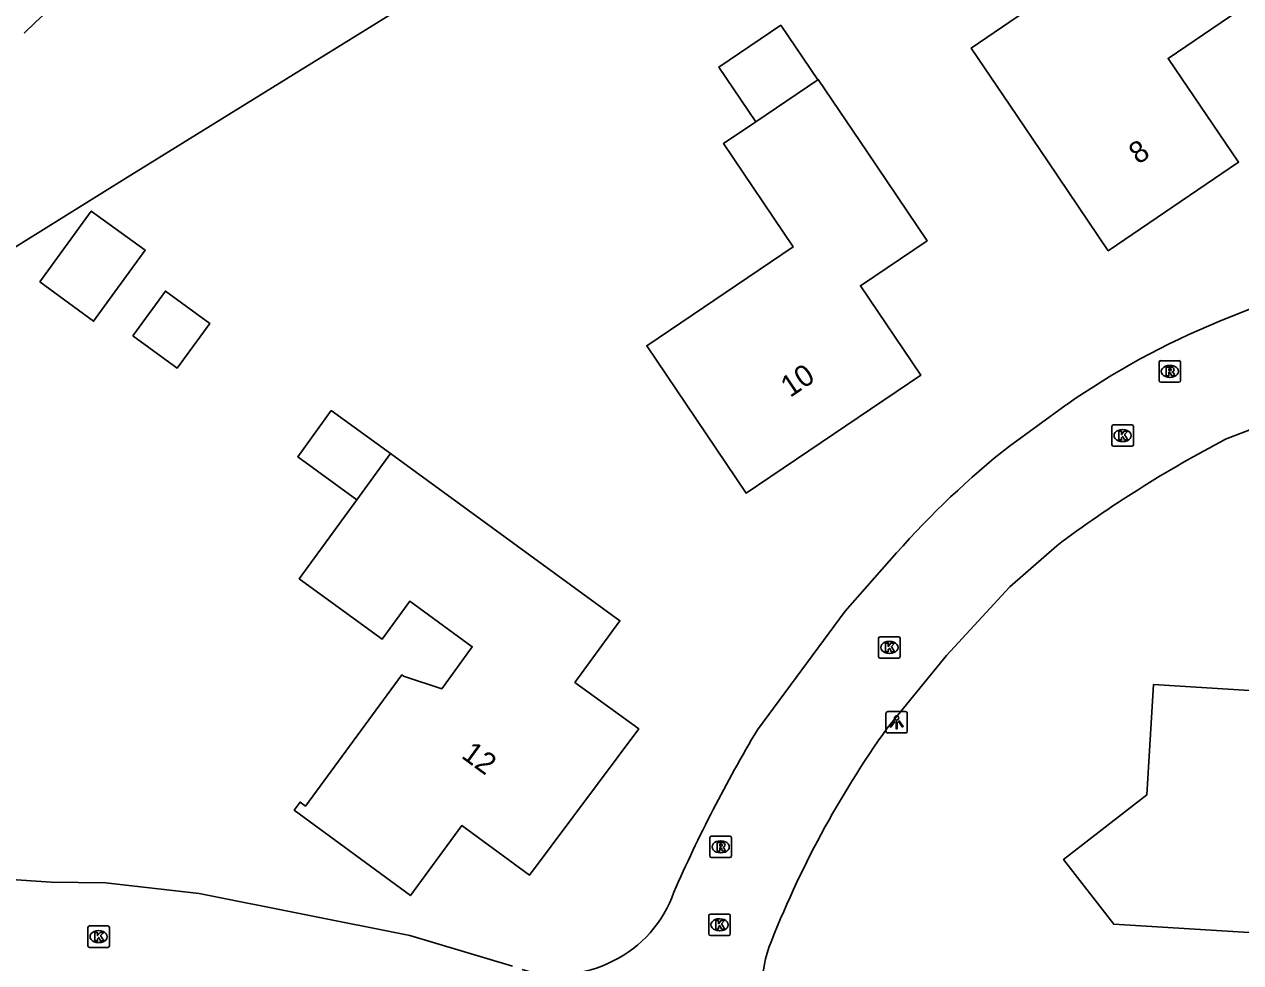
# Model space of a CAD drawing. Extents: x 163268 to 164360, y 381529 to 382285.
# Drawn here: x 163454.1 to 163510.8, y 381660.1 to 381703.8 of the extents above; entities that cross this region are included whole.
import ezdxf

# ---------------------------------------------------------------- set-up
doc = ezdxf.new("R2010")
doc.units = 0
for name, color, linetype in [('IMGEO_Kolk', 7, 'Continuous'), ('IMGEO_Lichtpunt', 7, 'Continuous'), ('IMGEO_Loofbos', 7, 'Continuous'), ('IMGEO_Pand', 7, 'Continuous'), ('IMGEO_Pand_nummerreeks', 7, 'Continuous'), ('IMGEO_Rijbaan_lokaal_open', 7, 'Continuous'), ('IMGEO_Rioolput', 7, 'Continuous'), ('IMGEO_Voetpad_halfverhard', 7, 'Continuous')]:
    doc.layers.add(name, color=color, linetype=linetype)

msp = doc.modelspace()

# ---------------------------------------------------------------- linework, layer by layer
at = {"layer": 'IMGEO_Kolk'}
for p, q in [((163504.757, 381684.204), (163504.757, 381685.056)), ((163504.832, 381685.13), (163505.684, 381685.13)), ((163505.245, 381684.91), (163505.27, 381684.91)), ((163505.758, 381685.056), (163505.758, 381684.204)), ((163505.268, 381684.35), (163505.243, 381684.35)), ((163505.684, 381684.13), (163504.832, 381684.13)), ((163493.89, 381674.335), (163493.89, 381675.187)), ((163493.965, 381675.261), (163494.817, 381675.261)), ((163494.891, 381675.187), (163494.891, 381674.335)), ((163494.378, 381675.041), (163494.403, 381675.041)), ((163494.817, 381674.261), (163493.965, 381674.261)), ((163494.401, 381674.481), (163494.376, 381674.481)), ((163485.977, 381661.414), (163485.977, 381662.266)), ((163486.052, 381662.34), (163486.904, 381662.34)), ((163486.465, 381662.12), (163486.49, 381662.12)), ((163486.978, 381662.266), (163486.978, 381661.414)), ((163457.045, 381660.862), (163457.045, 381661.714)), ((163457.12, 381661.788), (163457.972, 381661.788)), ((163457.533, 381661.568), (163457.558, 381661.568)), ((163458.046, 381661.714), (163458.046, 381660.862)), ((163486.488, 381661.56), (163486.463, 381661.56)), ((163457.556, 381661.008), (163457.531, 381661.008)), ((163486.904, 381661.34), (163486.052, 381661.34)), ((163457.972, 381660.788), (163457.12, 381660.788))]:
    msp.add_line(p, q, dxfattribs=at)
for points in [[(163504.757, 381684.204), (163504.757, 381685.056)], [(163504.832, 381685.13), (163505.684, 381685.13)], [(163505.078, 381684.83), (163505.201, 381684.83), (163505.201, 381684.679), (163505.331, 381684.83), (163505.495, 381684.83), (163505.349, 381684.679), (163505.502, 381684.43), (163505.35, 381684.43), (163505.265, 381684.594), (163505.201, 381684.527), (163505.201, 381684.43), (163505.078, 381684.43), (163505.078, 381684.83)], [(163505.758, 381685.056), (163505.758, 381684.204)], [(163505.684, 381684.13), (163504.832, 381684.13)], [(163493.89, 381674.335), (163493.89, 381675.187)], [(163493.965, 381675.261), (163494.817, 381675.261)], [(163494.891, 381675.187), (163494.891, 381674.335)], [(163494.211, 381674.961), (163494.334, 381674.961), (163494.334, 381674.81), (163494.464, 381674.961), (163494.628, 381674.961), (163494.482, 381674.81), (163494.635, 381674.561), (163494.483, 381674.561), (163494.398, 381674.725), (163494.334, 381674.658), (163494.334, 381674.561), (163494.211, 381674.561), (163494.211, 381674.961)], [(163494.817, 381674.261), (163493.965, 381674.261)], [(163485.977, 381661.414), (163485.977, 381662.266)], [(163486.052, 381662.34), (163486.904, 381662.34)], [(163486.978, 381662.266), (163486.978, 381661.414)], [(163457.045, 381660.862), (163457.045, 381661.714)], [(163457.12, 381661.788), (163457.972, 381661.788)], [(163458.046, 381661.714), (163458.046, 381660.862)], [(163486.298, 381662.04), (163486.421, 381662.04), (163486.421, 381661.889), (163486.551, 381662.04), (163486.715, 381662.04), (163486.569, 381661.889), (163486.722, 381661.64), (163486.57, 381661.64), (163486.485, 381661.804), (163486.421, 381661.737), (163486.421, 381661.64), (163486.298, 381661.64), (163486.298, 381662.04)], [(163457.366, 381661.488), (163457.489, 381661.488), (163457.489, 381661.337), (163457.619, 381661.488), (163457.783, 381661.488), (163457.637, 381661.337), (163457.79, 381661.088), (163457.638, 381661.088), (163457.553, 381661.252), (163457.489, 381661.185), (163457.489, 381661.088), (163457.366, 381661.088), (163457.366, 381661.488)], [(163486.904, 381661.34), (163486.052, 381661.34)], [(163457.972, 381660.788), (163457.12, 381660.788)]]:
    msp.add_lwpolyline(points, dxfattribs=at)
for centre, start, end in [((163504.834, 381685.054), 91.552, 178.448), ((163504.834, 381685.054), 91.552, 178.448), ((163505.682, 381685.054), 1.552, 88.448), ((163505.682, 381685.054), 1.552, 88.448), ((163504.834, 381684.206), 181.552, 268.448), ((163504.834, 381684.206), 181.552, 268.448), ((163505.682, 381684.206), 271.552, 358.448), ((163505.682, 381684.206), 271.552, 358.448), ((163493.967, 381675.185), 91.552, 178.448), ((163493.967, 381675.185), 91.552, 178.448), ((163494.815, 381675.185), 1.552, 88.448), ((163494.815, 381675.185), 1.552, 88.448), ((163493.967, 381674.337), 181.552, 268.448), ((163493.967, 381674.337), 181.552, 268.448), ((163494.815, 381674.337), 271.552, 358.448), ((163494.815, 381674.337), 271.552, 358.448), ((163486.054, 381662.264), 91.552, 178.448), ((163486.054, 381662.264), 91.552, 178.448), ((163486.902, 381662.264), 1.552, 88.448), ((163486.902, 381662.264), 1.552, 88.448), ((163457.122, 381661.712), 91.552, 178.448), ((163457.122, 381661.712), 91.552, 178.448), ((163457.97, 381661.712), 1.552, 88.448), ((163457.97, 381661.712), 1.552, 88.448), ((163486.054, 381661.416), 181.552, 268.448), ((163486.054, 381661.416), 181.552, 268.448), ((163486.902, 381661.416), 271.552, 358.448), ((163486.902, 381661.416), 271.552, 358.448), ((163457.122, 381660.864), 181.552, 268.448), ((163457.122, 381660.864), 181.552, 268.448), ((163457.97, 381660.864), 271.552, 358.448), ((163457.97, 381660.864), 271.552, 358.448)]:
    msp.add_arc(centre, 0.0765, start, end, dxfattribs=at)
for centre, major_axis, ratio, start_param, end_param in [((163505.244, 381684.63), (-0.387, 0.002), 0.722429, 4.712389, 7.853982), ((163505.269, 381684.63), (-0.39, 0.002), 0.717154, 1.570796, 4.712389), ((163494.377, 381674.761), (-0.387, 0.002), 0.722429, 4.712389, 7.853982), ((163494.402, 381674.761), (-0.39, 0.002), 0.717154, 1.570796, 4.712389), ((163486.464, 381661.84), (-0.387, 0.002), 0.722429, 4.712389, 7.853982), ((163486.489, 381661.84), (-0.39, 0.002), 0.717154, 1.570796, 4.712389), ((163457.532, 381661.288), (-0.387, 0.002), 0.722429, 4.712389, 7.853982), ((163457.557, 381661.288), (-0.39, 0.002), 0.717154, 1.570796, 4.712389)]:
    msp.add_ellipse(centre, major_axis=major_axis, ratio=ratio, start_param=start_param, end_param=end_param, dxfattribs=at)
at = {"layer": 'IMGEO_Lichtpunt'}
for p, q in [((163495.131, 381671.773), (163494.323, 381671.773)), ((163495.131, 381671.773), (163494.323, 381671.773)), ((163494.229, 381671.678), (163494.229, 381670.871)), ((163494.229, 381671.678), (163494.229, 381670.871)), ((163495.225, 381670.871), (163495.225, 381671.678)), ((163495.225, 381670.871), (163495.225, 381671.678)), ((163494.323, 381670.777), (163495.131, 381670.777)), ((163494.323, 381670.777), (163495.131, 381670.777))]:
    msp.add_line(p, q, dxfattribs=at)
for points in [[(163494.603, 381671.342), (163494.642, 381671.314), (163494.454, 381671.052), (163494.416, 381671.079), (163494.603, 381671.342)], [(163494.705, 381671.294), (163494.752, 381671.294), (163494.752, 381670.972), (163494.705, 381670.972), (163494.705, 381671.294)], [(163494.815, 381671.314), (163494.853, 381671.341), (163495.04, 381671.079), (163495.001, 381671.051), (163494.815, 381671.314)]]:
    msp.add_lwpolyline(points, dxfattribs=at)
msp.add_circle((163494.728, 381671.476), 0.0994, dxfattribs=at)
for centre, start, end in [((163494.323, 381671.678), 90, 180), ((163494.323, 381671.678), 90, 180), ((163495.131, 381671.678), 0, 90), ((163495.131, 381671.678), 0, 90), ((163494.323, 381670.871), 180, 270), ((163494.323, 381670.871), 180, 270), ((163495.131, 381670.871), 270, 0), ((163495.131, 381670.871), 270, 360)]:
    msp.add_arc(centre, 0.0946, start, end, dxfattribs=at)
at = {"layer": 'IMGEO_Loofbos'}
msp.add_lwpolyline([(163515.932, 381725.699), (163500, 381718.416), (163478.019, 381708.509), (163458.768, 381696.586), (163448.335, 381690.097), (163446.223, 381688.687), (163444.708, 381687.392), (163443.337, 381685.945), (163442.124, 381684.363), (163441.084, 381682.663), (163440.227, 381680.864), (163439.563, 381678.984), (163439.099, 381677.046), (163436.908, 381666.064)], dxfattribs=at)
at = {"layer": 'IMGEO_Pand'}
for points in [[(163501.788, 381697.387), (163500, 381700.029), (163498.207, 381702.679), (163500, 381703.899), (163502.907, 381705.876), (163498.168, 381712.863), (163502.82, 381716.017), (163506.727, 381710.255), (163507.865, 381708.577), (163510.672, 381704.438), (163507.376, 381702.203), (163510.659, 381697.361), (163504.586, 381693.243), (163501.788, 381697.387)], [(163491.049, 381701.194), (163489.332, 381703.741), (163486.447, 381701.795), (163488.164, 381699.249)], [(163488.164, 381699.249), (163486.656, 381698.232), (163489.904, 381693.416), (163483.083, 381688.817), (163484.917, 381686.099), (163487.711, 381681.953), (163495.849, 381687.441), (163493.039, 381691.609), (163496.144, 381693.702), (163493.348, 381697.849), (163491.078, 381701.214), (163491.049, 381701.194)], [(163488.164, 381699.249), (163491.049, 381701.194)], [(163454.799, 381691.784), (163457.206, 381695.091), (163459.719, 381693.262), (163457.312, 381689.955), (163454.799, 381691.784)], [(163459.146, 381689.28), (163460.661, 381691.362), (163462.727, 381689.858), (163461.212, 381687.776), (163459.146, 381689.28)], [(163469.578, 381681.64), (163466.822, 381683.646), (163468.386, 381685.794), (163471.141, 381683.788)], [(163471.141, 381683.788), (163481.831, 381676.005), (163479.738, 381673.13), (163482.71, 381670.966), (163477.628, 381664.153), (163474.473, 381666.471), (163472.073, 381663.204), (163466.657, 381667.183), (163466.93, 381667.554), (163467.179, 381667.37), (163471.668, 381673.479), (163471.749, 381673.42), (163473.532, 381672.835), (163474.954, 381674.791), (163472.04, 381676.909), (163470.761, 381675.149), (163466.896, 381677.957), (163469.578, 381681.64)], [(163469.578, 381681.64), (163471.141, 381683.788)], [(163525.256, 381660.614), (163504.847, 381661.869), (163502.509, 381664.883), (163506.381, 381667.887), (163506.697, 381673.027), (163515.63, 381672.477), (163516.992, 381673.846), (163518.175, 381672.321), (163525.162, 381671.891), (163524.846, 381666.751), (163527.972, 381662.721), (163525.256, 381660.614)]]:
    msp.add_lwpolyline(points, dxfattribs=at)
at = {"layer": 'IMGEO_Rijbaan_lokaal_open'}
for points in [[(163510.055, 381684.458), (163513.655, 381685.838), (163523.182, 381688.767), (163532.966, 381691.972), (163539.446, 381694.524), (163545.294, 381697.408), (163552.771, 381702.059), (163557.229, 381705.595), (163562.772, 381711.146)], [(163509.739, 381689.939), (163515.167, 381692.112), (163530.227, 381696.265), (163534.828, 381697.975), (163539.797, 381700.104), (163543.47, 381702.108), (163550.9, 381706.962)], [(163499.985, 381684.14), (163502.635, 381686.062)], [(163488.242, 381670.925), (163492.326, 381676.445), (163494.725, 381679.161)], [(163494.287, 381671.006), (163497.045, 381674.38), (163500, 381677.591), (163502.194, 381679.501)], [(163437.182, 381666.013), (163442.176, 381665.079), (163448.608, 381664.27), (163455.329, 381663.829), (163457.86, 381663.79), (163462.224, 381663.302), (163472.048, 381661.348), (163476.829, 381659.912)]]:
    msp.add_lwpolyline(points, dxfattribs=at)
for centre, radius, start, end in [((163523.663, 381655.979), 36.704, 112.2938, 124.9531), ((163536.262, 381634.186), 56.693, 117.5334, 126.9361), ((163525.069, 381652.373), 40.477, 128.2949, 138.561), ((163546.847, 381635.976), 68.235, 149.1904, 156.33561), ((163532.617, 381643.742), 47.037, 144.5755, 158.7656), ((163479.032, 381665.204), 5.627, 295.922, 340.9126), ((163494.731, 381658.773), 6.287, 161.4036, 237.6877), ((163478.903, 381665.211), 5.691, 253.5129, 297.0603)]:
    msp.add_arc(centre, radius, start, end, dxfattribs=at)
at = {"layer": 'IMGEO_Rioolput'}
for p, q in [((163506.957, 381687.193), (163506.957, 381688.045)), ((163507.032, 381688.119), (163507.884, 381688.119)), ((163507.445, 381687.899), (163507.47, 381687.899)), ((163507.958, 381688.045), (163507.958, 381687.193)), ((163507.884, 381687.119), (163507.032, 381687.119)), ((163507.468, 381687.339), (163507.443, 381687.339)), ((163486.03, 381665.045), (163486.03, 381665.897)), ((163486.105, 381665.971), (163486.957, 381665.971)), ((163486.518, 381665.751), (163486.543, 381665.751)), ((163487.031, 381665.897), (163487.031, 381665.045)), ((163486.957, 381664.971), (163486.105, 381664.971)), ((163486.541, 381665.191), (163486.516, 381665.191))]:
    msp.add_line(p, q, dxfattribs=at)
for points in [[(163506.957, 381687.193), (163506.957, 381688.045)], [(163507.032, 381688.119), (163507.884, 381688.119)], [(163507.546, 381687.817), (163507.294, 381687.819), (163507.294, 381687.419)], [(163507.472, 381687.738), (163507.418, 381687.738), (163507.418, 381687.657)], [(163507.418, 381687.657), (163507.47, 381687.657)], [(163507.958, 381688.045), (163507.958, 381687.193)], [(163507.884, 381687.119), (163507.032, 381687.119)], [(163507.294, 381687.419), (163507.418, 381687.419), (163507.418, 381687.581), (163507.429, 381687.581)], [(163507.476, 381687.552), (163507.547, 381687.419), (163507.687, 381687.419), (163507.622, 381687.545)], [(163486.03, 381665.045), (163486.03, 381665.897)], [(163486.105, 381665.971), (163486.957, 381665.971)], [(163486.619, 381665.669), (163486.367, 381665.671), (163486.367, 381665.271)], [(163486.545, 381665.59), (163486.491, 381665.59), (163486.491, 381665.509)], [(163487.031, 381665.897), (163487.031, 381665.045)], [(163486.957, 381664.971), (163486.105, 381664.971)], [(163486.367, 381665.271), (163486.491, 381665.271), (163486.491, 381665.433), (163486.502, 381665.433)], [(163486.491, 381665.509), (163486.543, 381665.509)], [(163486.549, 381665.404), (163486.62, 381665.271), (163486.76, 381665.271), (163486.695, 381665.397)]]:
    msp.add_lwpolyline(points, dxfattribs=at)
for centre, radius, start, end in [((163507.034, 381688.043), 0.0765, 91.552, 178.448), ((163507.034, 381688.043), 0.0765, 91.552, 178.448), ((163507.454, 381687.846), 0.19, 274.7715, 282.9687), ((163507.478, 381687.642), 0.0964, 77.0061, 93.1865), ((163507.492, 381687.699), 0.0378, 276.6634, 79.6772), ((163507.545, 381687.707), 0.109, 350.3612, 89.416), ((163507.543, 381687.707), 0.112, 277.5842, 350.9817), ((163507.882, 381688.043), 0.0765, 1.552, 88.448), ((163507.882, 381688.043), 0.0765, 1.552, 88.448), ((163507.034, 381687.195), 0.0765, 181.552, 268.448), ((163507.034, 381687.195), 0.0765, 181.552, 268.448), ((163507.428, 381687.528), 0.0533, 26.0293, 88.6989), ((163507.527, 381687.492), 0.108, 29.5134, 73.7905), ((163507.882, 381687.195), 0.0765, 271.552, 358.448), ((163507.882, 381687.195), 0.0765, 271.552, 358.448), ((163486.107, 381665.895), 0.0765, 91.552, 178.448), ((163486.107, 381665.895), 0.0765, 91.552, 178.448), ((163486.527, 381665.698), 0.19, 274.7715, 282.9687), ((163486.551, 381665.494), 0.0964, 77.0061, 93.1865), ((163486.565, 381665.551), 0.0378, 276.6634, 79.6772), ((163486.618, 381665.559), 0.109, 350.3612, 89.416), ((163486.616, 381665.559), 0.112, 277.5842, 350.9817), ((163486.955, 381665.895), 0.0765, 1.552, 88.448), ((163486.955, 381665.895), 0.0765, 1.552, 88.448), ((163486.107, 381665.047), 0.0765, 181.552, 268.448), ((163486.107, 381665.047), 0.0765, 181.552, 268.448), ((163486.501, 381665.38), 0.0533, 26.0293, 88.6989), ((163486.6, 381665.344), 0.108, 29.5134, 73.7905), ((163486.955, 381665.047), 0.0765, 271.552, 358.448), ((163486.955, 381665.047), 0.0765, 271.552, 358.448)]:
    msp.add_arc(centre, radius, start, end, dxfattribs=at)
for centre, major_axis, ratio, start_param, end_param in [((163507.444, 381687.619), (-0.387, 0.002), 0.722429, 4.712389, 7.853982), ((163507.469, 381687.619), (-0.39, 0.002), 0.717154, 1.570796, 4.712389), ((163486.517, 381665.471), (-0.387, 0.002), 0.722429, 4.712389, 7.853982), ((163486.542, 381665.471), (-0.39, 0.002), 0.717154, 1.570796, 4.712389)]:
    msp.add_ellipse(centre, major_axis=major_axis, ratio=ratio, start_param=start_param, end_param=end_param, dxfattribs=at)
at = {"layer": 'IMGEO_Voetpad_halfverhard'}
for centre, radius, start, end in [((163524.381, 381631.519), 100.521, 120.97533, 134.37308), ((163515.383, 381643.193), 87.773, 122.38287, 138.00382)]:
    msp.add_arc(centre, radius, start, end, dxfattribs=at)

# ---------------------------------------------------------------- texts
at = {"layer": 'IMGEO_Pand_nummerreeks'}
for s, rotation, p in [('8', 34.1426, (163505.984, 381697.235)), ('10', 33.9936, (163489.764, 381686.377)), ('12', 323.6974, (163474.397, 381669.653))]:
    msp.add_text(s, height=1, rotation=rotation, dxfattribs=at).set_placement(p)

doc.saveas('drawing.dxf')
